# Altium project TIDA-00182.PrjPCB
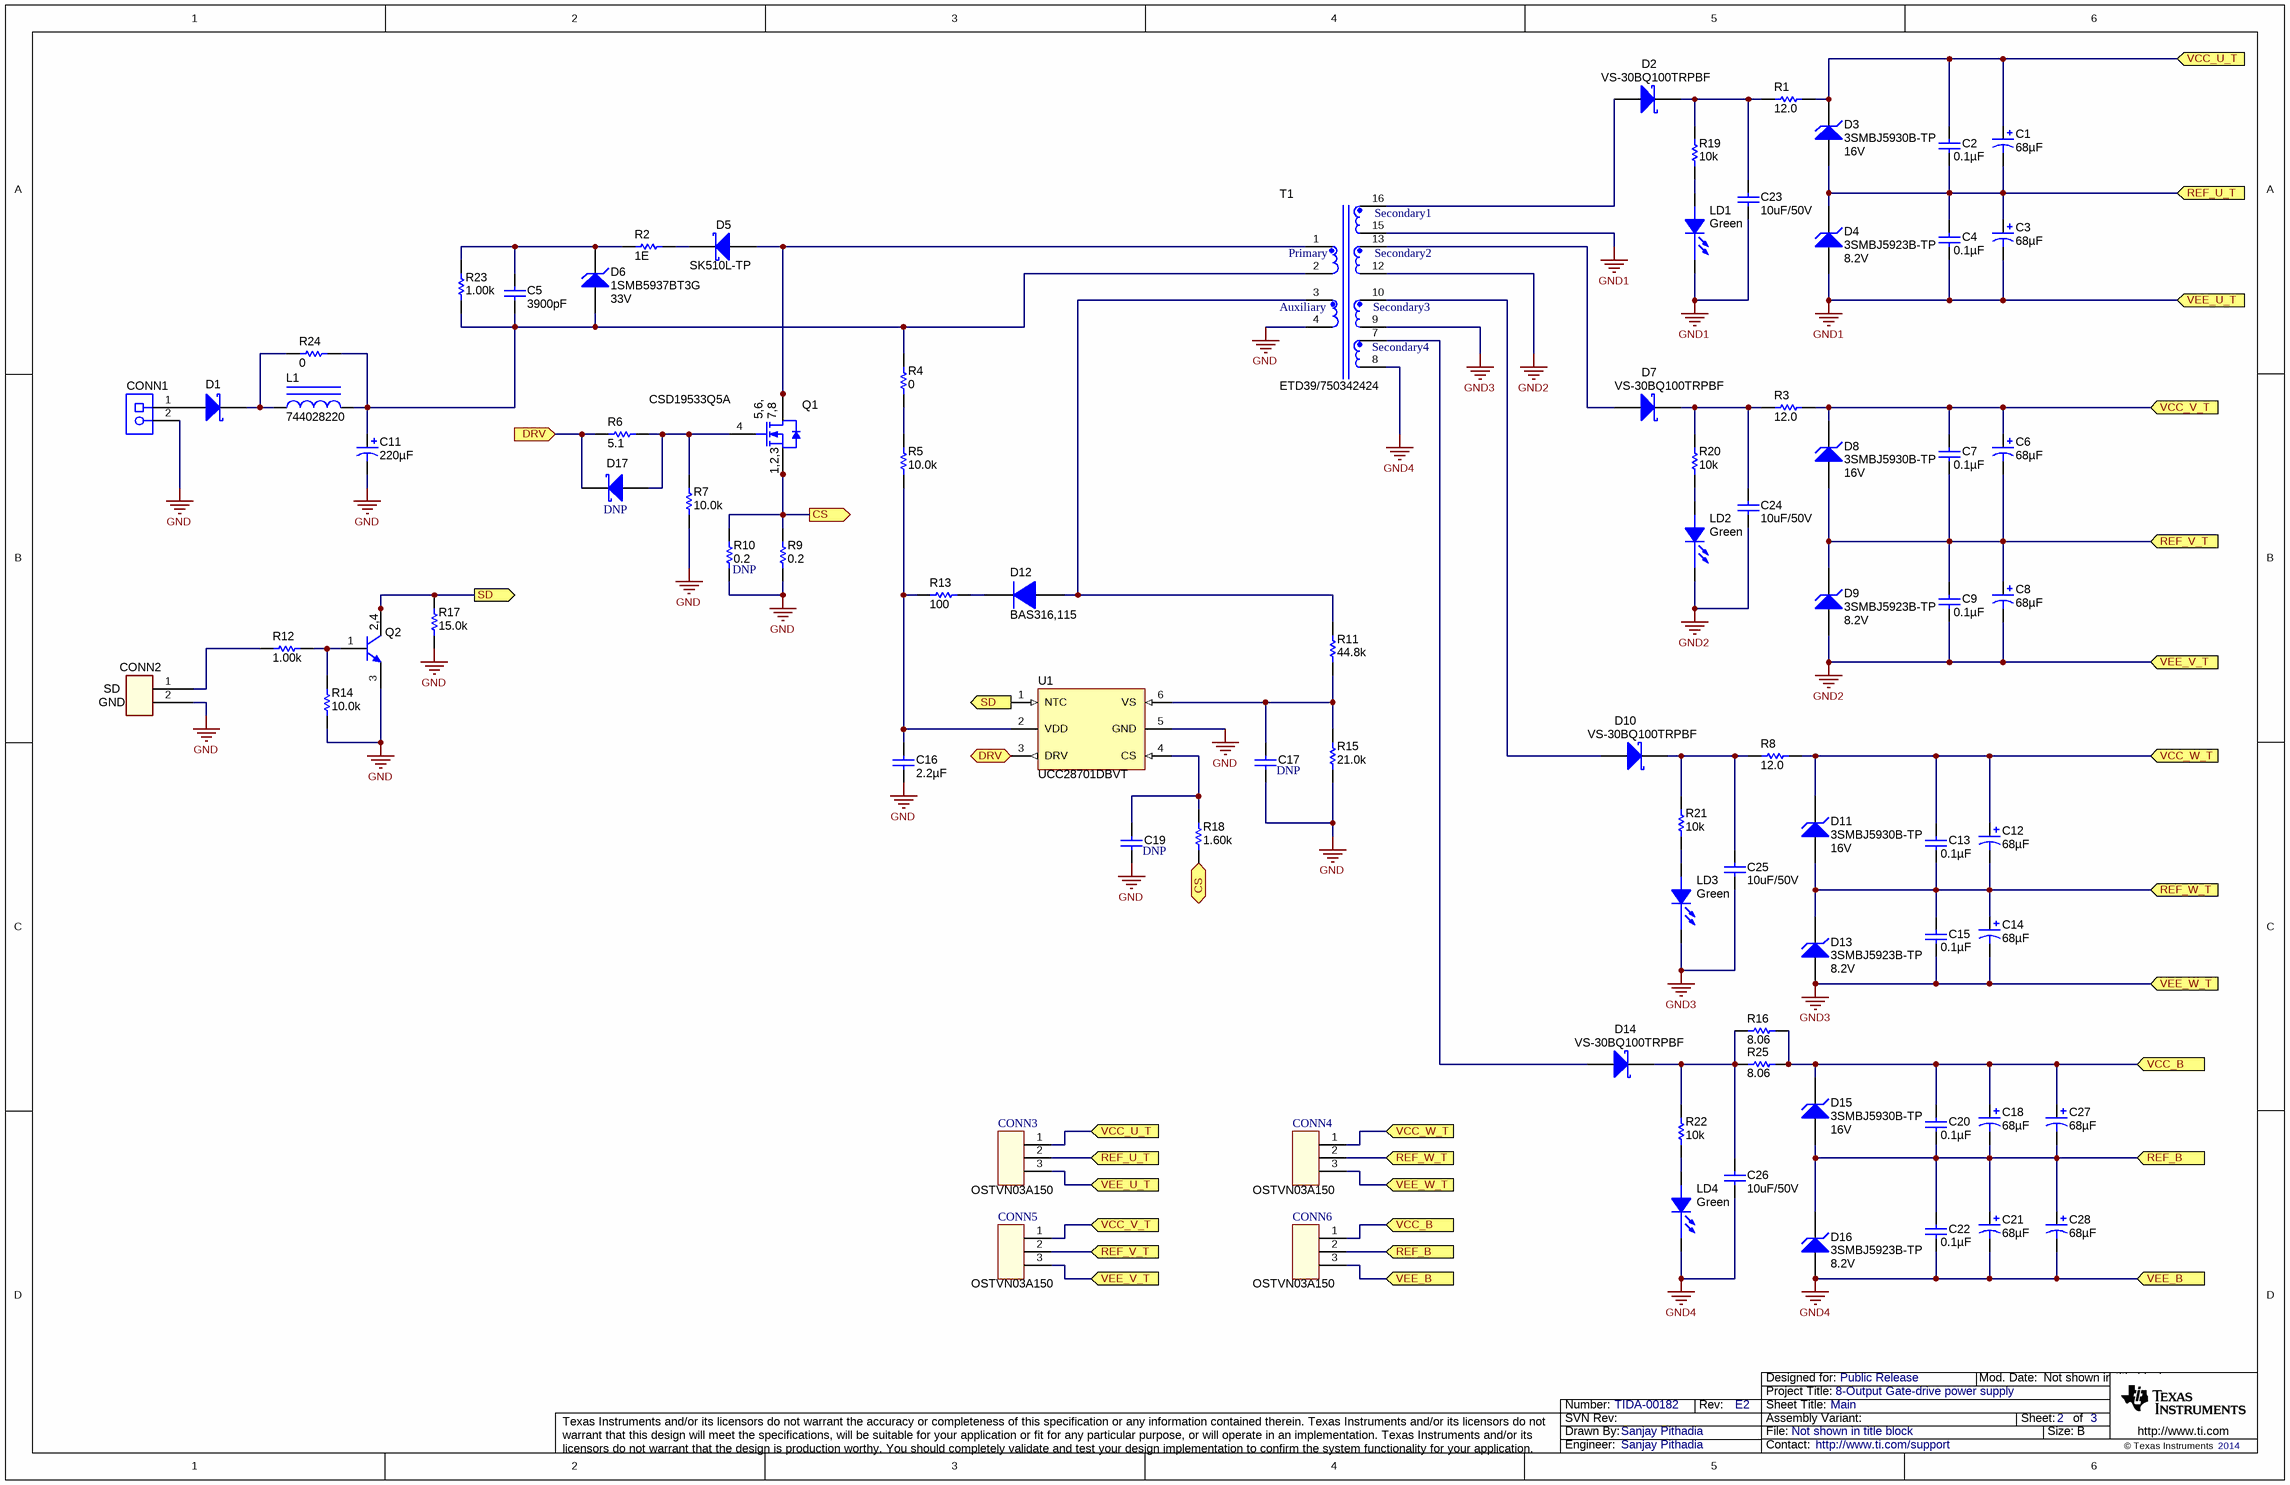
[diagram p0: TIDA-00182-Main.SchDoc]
CopyrightYear: 2014; PCB_Layout: Sharanu; PCB_Rev: E2; PRJ_Customer: Public Release; PRJ_Engineer: Sanjay Pithadia; PRJ_Number: TIDA-00182; PRJ_Title: 8-Output Gate-drive power supply; SCH_Rev: E2; TechSupport: http://www.ti.com/support
3 sheets, 102 parts. Net scope: flat (ports and power ports of the same name join across sheets).
Board file: TIDA-00182.PcbDoc
Sheets:
  TIDA-00182-Cover.SchDoc
  TIDA-00182-Main.SchDoc
  Hardware_ANSI-B.SchDoc

## Sheet TIDA-00182-Cover.SchDoc
size 431 x 279 mm; Date: Not shown in title block; ApprovedBy: Not shown in title block; CheckedBy: Not shown in title block; Author: Not shown in title block; CompanyName: Not shown in title block; Engineer: Not shown in title block; Organization: Not shown in title block; Address1: Not shown in title block; Address2: Not shown in title block; Address3: Not shown in title block; Address4: Not shown in title block; DocumentNumber: 1; Revision: Use project parameter SCH_Rev; SheetNumber: 1; SheetTotal: 3; PageSetup: Record=PageOptions|CenterHorizontal=True|CenterVertical=True|PrintScale=1.00|XCorrection=1.00|YCorrection=1.00|PrintKind=0|BorderSize=5000000|LeftOffset=0|BottomOffset=0|Orientation=2|PaperLength=1000|PaperWidth=1000|Scale=100|PaperSource=15|PrintQuality=600|MediaType=1|DitherType=10|PaperKind=Letter|PrintScaleMode=1

## Sheet TIDA-00182-Main.SchDoc: Main
size 431 x 279 mm; Date: Not shown in title block; ApprovedBy: Not shown in title block; CheckedBy: Not shown in title block; Author: Not shown in title block; CompanyName: Not shown in title block; DrawnBy: Sanjay Pithadia; Engineer: Not shown in title block; Organization: Not shown in title block; Address1: Not shown in title block; Address2: Not shown in title block; Address3: Not shown in title block; Address4: Not shown in title block; DocumentNumber: 2; Revision: Use project parameter SCH_Rev; SheetNumber: 2; SheetTotal: 3; PageSetup: Record=PageOptions|CenterHorizontal=True|CenterVertical=True|PrintScale=1.00|XCorrection=1.00|YCorrection=1.00|PrintKind=0|BorderSize=5000000|LeftOffset=0|BottomOffset=0|Orientation=2|PaperLength=1000|PaperWidth=1000|Scale=100|PaperSource=15|PrintQuality=600|MediaType=1|DitherType=10|PaperKind=Letter|PrintScaleMode=1

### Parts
C1  ValueDisplayed: 68µF  [SM_RADIAL_6.3BMM]  (hidden comment: EEH-ZA1V680XP)
C2  ValueDisplayed: 0.1µF  [0805_HV]  (hidden comment: 08055C104JAT2A)
C3  ValueDisplayed: 68µF  [SM_RADIAL_6.3BMM]  (hidden comment: EEH-ZA1V680XP)
C4  ValueDisplayed: 0.1µF  [0805_HV]  (hidden comment: 08055C104JAT2A)
C5  ValueDisplayed: 3900pF  [0805_HV]  (hidden comment: GRM219R72A392KA01D)
C6  ValueDisplayed: 68µF  [SM_RADIAL_6.3BMM]  (hidden comment: EEH-ZA1V680XP)
C7  ValueDisplayed: 0.1µF  [0805_HV]  (hidden comment: 08055C104JAT2A)
C8  ValueDisplayed: 68µF  [SM_RADIAL_6.3BMM]  (hidden comment: EEH-ZA1V680XP)
C9  ValueDisplayed: 0.1µF  [0805_HV]  (hidden comment: 08055C104JAT2A)
C11  ValueDisplayed: 220µF  [SM_RADIAL_F]  (hidden comment: EEE-FK1V221P)
C12  ValueDisplayed: 68µF  [SM_RADIAL_6.3BMM]  (hidden comment: EEH-ZA1V680XP)
C13  ValueDisplayed: 0.1µF  [0805_HV]  (hidden comment: 08055C104JAT2A)
C14  ValueDisplayed: 68µF  [SM_RADIAL_6.3BMM]  (hidden comment: EEH-ZA1V680XP)
C15  ValueDisplayed: 0.1µF  [0805_HV]  (hidden comment: 08055C104JAT2A)
C16  ValueDisplayed: 2.2µF  [0805_HV]  (hidden comment: C2012X5R1H225K125AB)
C17  Fitted: DNP  [0805_HV]  (hidden comment: 08053D334KAT2A)
C18  ValueDisplayed: 68µF  [SM_RADIAL_6.3BMM]  (hidden comment: EEH-ZA1V680XP)
C19  Fitted: DNP  [0805_HV]  (hidden comment: C2012X7R1H102K)
C20  ValueDisplayed: 0.1µF  [0805_HV]  (hidden comment: 08055C104JAT2A)
C21  ValueDisplayed: 68µF  [SM_RADIAL_6.3BMM]  (hidden comment: EEH-ZA1V680XP)
C22  ValueDisplayed: 0.1µF  [0805_HV]  (hidden comment: 08055C104JAT2A)
C23  10uF/50V  [1206_190]
C24  10uF/50V  [1206_190]
C25  10uF/50V  [1206_190]
C26  10uF/50V  [1206_190]
C27  ValueDisplayed: 68µF  [SM_RADIAL_6.3BMM]  (hidden comment: EEH-ZA1V680XP)
C28  ValueDisplayed: 68µF  [SM_RADIAL_6.3BMM]  (hidden comment: EEH-ZA1V680XP)
CONN1  282841-2  [TEC_282841-2]  (value not drawn)
CONN2  CON-OSTVN02A150  [CN2_MTB_P100_PD80_D1.1_S5.54X6.5_STACK]  (value not drawn)
CONN3  PartNumber: OSTVN03A150  [TB_OSTVN03A150_3P]  (hidden comment: CON-OSTVN03A150)
CONN4  PartNumber: OSTVN03A150  [TB_OSTVN03A150_3P]  (hidden comment: CON-OSTVN03A150)
CONN5  PartNumber: OSTVN03A150  [TB_OSTVN03A150_3P]  (hidden comment: CON-OSTVN03A150)
CONN6  PartNumber: OSTVN03A150  [TB_OSTVN03A150_3P]  (hidden comment: CON-OSTVN03A150)
D1  B260A-13-F  [SMA]  (value not drawn)
D2  VS-30BQ100TRPBF  [SMC]
D3  3SMBJ5930B-TP  value 16V  [SMB]
D4  3SMBJ5923B-TP  value 8.2V  [SMB]
D5  SK510L-TP  [SMC]
D6  1SMB5937BT3G  value 33V  [SMB]
D7  VS-30BQ100TRPBF  [SMC]
D8  3SMBJ5930B-TP  value 16V  [SMB]
D9  3SMBJ5923B-TP  value 8.2V  [SMB]
D10  VS-30BQ100TRPBF  [SMC]
D11  3SMBJ5930B-TP  value 16V  [SMB]
D12  BAS316,115  [sod-323]
D13  3SMBJ5923B-TP  value 8.2V  [SMB]
D14  VS-30BQ100TRPBF  [SMC]
D15  3SMBJ5930B-TP  value 16V  [SMB]
D16  3SMBJ5923B-TP  value 8.2V  [SMB]
D17  Fitted: DNP  [SOD-123]  (hidden comment: MBR0520LT1G)
L1  744028220  [WE-TPC_2811]
LD1  value Green  [LED0603AA]  (hidden comment: LED_LG L29K-G2J1-24-Z)
LD2  value Green  [LED0603AA]  (hidden comment: LED_LG L29K-G2J1-24-Z)
LD3  value Green  [LED0603AA]  (hidden comment: LED_LG L29K-G2J1-24-Z)
LD4  value Green  [LED0603AA]  (hidden comment: LED_LG L29K-G2J1-24-Z)
Q1  CSD19533Q5A  [TRANS_NexFET_Q5A]
Q2  2DD1664R-13  [SOT-89-3]  (value not drawn)
R1  value 12.0  [1206]  (hidden comment: RC1206FR-0712RL)
R2  value 1E  [1206]  (hidden comment: CRCW12061K00FKEA)
R3  value 12.0  [1206]  (hidden comment: RC1206FR-0712RL)
R4  value 0  [1206]  (hidden comment: RC1206JR-070RL)
R5  value 10.0k  [1206]  (hidden comment: ERJ-8ENF1002V)
R6  value 5.1  [0805_HV]  (hidden comment: CRCW08055R10JNEA)
R7  value 10.0k  [0805_HV]  (hidden comment: RG2012P-103-B-T5)
R8  value 12.0  [1206]  (hidden comment: RC1206FR-0712RL)
R9  value 0.2  [1206]  (hidden comment: CSR1206FKR200)
R10  value 0.2  Fitted: DNP  [1206]  (hidden comment: CSR1206FKR200)
R11  value 44.8k  [0805_HV]  (hidden comment: RT0805BRD0744K8L)
R12  value 1.00k  [0805_HV]  (hidden comment: CRCW08051K00FKEA)
R13  value 100  [0805_HV]  (hidden comment: CRCW0805100RFKEA)
R14  value 10.0k  [0805_HV]  (hidden comment: RG2012P-103-B-T5)
R15  value 21.0k  [0805_HV]  (hidden comment: CRCW080521K0FKEA)
R16  value 8.06  [1206]  (hidden comment: CRCW12068R06FKEA)
R17  value 15.0k  [0805_HV]  (hidden comment: RG2012P-153-B-T5)
R18  value 1.60k  [0805_HV]  (hidden comment: RR1220P-162-D)
R19  value 10k  [0805_HV]  (hidden comment: CRCW080510K0JNEA)
R20  value 10k  [0805_HV]  (hidden comment: CRCW080510K0JNEA)
R21  value 10k  [0805_HV]  (hidden comment: CRCW080510K0JNEA)
R22  value 10k  [0805_HV]  (hidden comment: CRCW080510K0JNEA)
R23  value 1.00k  [1206]  (hidden comment: RC1206FR-071KL)
R24  value 0  [1206]  (hidden comment: RC1206JR-070RL)
R25  value 8.06  [1206]  (hidden comment: CRCW12068R06FKEA)
T1  ETD39/750342424  [XFORMER_ETD39]
U1  UCC28701DBVT  [DBV-6]

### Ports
CS (in), CS (out), DRV (in), DRV (out), REF_B, REF_U_T, REF_V_T, REF_W_T, SD (in), SD (out), VCC_B, VCC_U_T, VCC_V_T, VCC_W_T, VEE_B, VEE_U_T, VEE_V_T, VEE_W_T

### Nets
GND: C11.2(-) C16.2 C17.2 C19.2 CONN1.2 CONN2.2 Q2.3(E) R7.1 R9.1 R10.1 R14.1 R15.1 R17.1 T1.4 U1.5(GND)
GND1: C3.2(-) C4.2 C23.2 CONN3.3 D4.2(A) LD1.1(C) T1.15 ; port VEE_U_T
GND2: C8.2(-) C9.2 C24.2 CONN5.3 D9.2(A) LD2.1(C) T1.12 ; port VEE_V_T
GND3: C14.2(-) C15.2 C25.2 CONN4.3 D13.2(A) LD3.1(C) T1.9 ; port VEE_W_T
GND4: C21.2(-) C22.2 C26.2 C28.2(-) CONN6.3 D16.2(A) LD4.1(C) T1.8 ; port VEE_B
CS: Q1.1(S) Q1.2(S) Q1.3(S) R9.2 R10.2 R18.1 ; port CS
DRV: D17.1(K) R6.2 U1.3(DRV) ; port DRV
REF_B: C18.2(-) C20.2 C21.1(+) C22.1 C27.2(-) C28.1(+) CONN6.2 D15.2(A) D16.1(K) ; port REF_B
REF_U_T: C1.2(-) C2.2 C3.1(+) C4.1 CONN3.2 D3.2(A) D4.1(K) ; port REF_U_T
REF_V_T: C6.2(-) C7.2 C8.1(+) C9.1 CONN5.2 D8.2(A) D9.1(K) ; port REF_V_T
REF_W_T: C12.2(-) C13.2 C14.1(+) C15.1 CONN4.2 D11.2(A) D13.1(K) ; port REF_W_T
SD: Q2.2(C) Q2.4(C) R17.2 U1.1(NTC) ; port SD
VCC_B: C18.1(+) C20.1 C27.1(+) CONN6.1 D15.1(K) R16.2 R25.2 ; port VCC_B
VCC_U_T: C1.1(+) C2.1 CONN3.1 D3.1(K) R1.2 ; port VCC_U_T
VCC_V_T: C6.1(+) C7.1 CONN5.1 D8.1(K) R3.2 ; port VCC_V_T
VCC_W_T: C12.1(+) C13.1 CONN4.1 D11.1(K) R8.2 ; port VCC_W_T
NetC5_1: C5.1 D6.1(K) R2.1 R23.2
NetC5_2: C5.2 C11.1(+) D6.2(A) L1.2 R4.2 R23.1 R24.1 T1.2
NetC16_1: C16.1 R5.1 R13.1 U1.2(VDD)
NetC17_1: C17.1 R11.1 R15.2 U1.6(VS)
NetC19_1: C19.1 R18.2 U1.4(CS)
NetC23_1: C23.1 D2.1(K) R1.1 R19.1
NetC24_1: C24.1 D7.1(K) R3.1 R20.1
NetC25_1: C25.1 D10.1(K) R8.1 R21.1
NetC26_1: C26.1 D14.1(K) R16.1 R22.1 R25.1
NetCONN1_1: CONN1.1 D1.2(A)
NetCONN2_1: CONN2.1 R12.2
NetD1_1: D1.1(K) L1.1 R24.2
NetD2_2: D2.2(A) T1.16
NetD5_1: D5.1(K) R2.2
NetD5_2: D5.2(A) Q1.5(D) Q1.6(D) Q1.7(D) Q1.8(D) Q1.9(D) T1.1
NetD7_2: D7.2(A) T1.13
NetD10_2: D10.2(A) T1.10
NetD12_1: D12.1(K) R13.2
NetD12_2: D12.2(A) R11.2 T1.3
NetD14_2: D14.2(A) T1.7
NetD17_2: D17.2(A) Q1.4(G) R6.1 R7.2
NetLD1_2: LD1.2(A) R19.2
NetLD2_2: LD2.2(A) R20.2
NetLD3_2: LD3.2(A) R21.2
NetLD4_2: LD4.2(A) R22.2
NetQ2_1: Q2.1(B) R12.1 R14.2
NetR4_1: R4.1 R5.2

Not connected (* = marked no-connect by the designer): T1 5 6 11 14

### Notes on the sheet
- (near CONN2) SD
- (near CONN2) GND

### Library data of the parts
C1 C3 C6 C8 C12 C14 C18 C21 C27 C28 = UUD1V680MCL1GS: CAP ALUM 68UF 35V 20% SMD; Manufacturer: Panasonic Electronic Components; Polarized: Y; CompType: Capacitor; U/M: EA; Cap_F: 0.000068; Tolerance_%: 20; Value1: 0.34 ohm; VDC_V: 35; ESR_Ohm: 0.34; IRMS_A: 0.28; TaMin_C: -55; TaMax_C: 105; Cap_Case: 6.60mm x 6.60mm
C2 C4 C7 C9 C13 C15 C20 C22 = 08055C104JAT2A: CAP, CERM, 0.1uF, 50V, +/-5%, X7R, 0805; Manufacturer: AVX; Polarized: N; CompType: Capacitor; U/M: EA; Cap_F: 0.0000001; Tolerance_%: 5; ESR_Ohm: 0.024; Value1: 0.024 ohm; VDC_V: 50; TaMin_C: -55; TaMax_C: 125; Cap_Case: 0805
C5 = GRM219R72A392KA01D: CAP, CERM, 3900pF, 100V, +/-10%, X7R, 0805; Manufacturer: MuRata; Polarized: N; CompType: Capacitor; U/M: EA; Cap_F: 0.0000000039; Tolerance_%: 10; Value1: Unknown; VDC_V: 100; TaMin_C: -55; TaMax_C: 125; Cap_Case: 0805
C11 = EEE-FK1V221P: CAP, AL, 220uF, 35V, +/-20%, 0.16 ohm, SMD; Manufacturer: Panasonic; Polarized: Y; CompType: Capacitor; U/M: EA; Cap_F: 0.00022; Tolerance_%: 20; VDC_V: 35; ESR_Ohm: 0.16; IRMS_A: 0.6; TaMin_C: -55; TaMax_C: 105; Cap_Case: F
C16 = C2012X5R1H225K125AB: CAP, CERM, 2.2uF, 50V, +/-10%, X5R, 0805; Manufacturer: TDK; Polarized: N; CompType: Capacitor; U/M: EA; Cap_F: 0.0000022; Tolerance_%: 10; Value1: Unknown; VDC_V: 50; TaMin_C: -55; TaMax_C: 85; Cap_Case: 0805
C17 = 08053D334KAT2A: CAP, CERM, 0.33uF, 25V, +/-10%, X5R, 0805; Manufacturer: AVX; Polarized: N; CompType: Capacitor; ValueDisplayed: 0.33µF; U/M: EA; Cap_F: 0.00000033; Tolerance_%: 10; ESR_Ohm: 0.02; Value1: 0.02 ohm; VDC_V: 25; TaMin_C: -55; TaMax_C: 85; Cap_Case: 0805
C19 = C2012X7R1H102K: CAP, CERM, 1000pF, 50V, +/-10%, X7R, 0805; Manufacturer: TDK; Polarized: N; CompType: Capacitor; U/M: EA; Cap_F: 0.000000001; Tolerance_%: 10; ESR_Ohm: 0.28; Value1: 0.28 ohm; VDC_V: 50; TaMin_C: -55; TaMax_C: 125; Cap_Case: 0805
C23-C26 = CGA5L3X5R1H106K160AB: CAP, CERM, 10uF, 50V, +/-10%, X5R, 1206_190; Manufacturer: TDK; Polarized: N; CompType: Capacitor; ValueDisplayed: 10µF; U/M: EA; Cap_F: 0.00001; Tolerance_%: 10; Value1: Unknown; VDC_V: 50; TaMin_C: -55; TaMax_C: 85
CONN1 = 282841-2: Terminal Block, 2x1, 5.08mm, TH; Manufacturer: TE Connectivity; SymbolCreator: a0412235; U/M: EA
CONN2 = CON-OSTVN02A150: Terminal Block, 4x1, 2.54mm, TH; Manufacturer: On Shore Technology Inc; SymbolCreator: x0120606
CONN3-CONN6 = CON-OSTVN03A150: CONN TERM BLOCK 2.54MM 3POS PCB; Manufacturer: On Shore Technology Inc; SymbolCreator: x0120606; CompType: Terminal Block
D1 = B260A-13-F: Diode, Schottky, 60V, 2A, SMA; Manufacturer: Diodes Inc.; U/M: EA; Vf_V: 0.7; Value2: 0.7V; Io_A: 2; Vr_V: 60; TJmax_C: 150; RJC_CperW: 20
D2 D7 D10 D14 = VS-30BQ100TRPBF: Diode, Schottky, 100V, 3A, SMC; Manufacturer: Vishay-Semiconductor; U/M: EA; Vf_V: 0.62; Value2: 0.62V; Io_A: 3; Vr_V: 100; TJmax_C: 175; RJC_CperW: 46
D3 D8 D11 D15 = 1SMB5930BT3G: DIODE ZENER 16V 3W DO214AA; Manufacturer: Micro Commercial Co; SymbolCreator: a0412235; U/M: EA; Power_W: 3; Vz_V: 16; RJA_CperW: 226
D4 D9 D13 D16 = 1SMB5930BT3G: DIODE ZENER 8.2V 3W DO214AA; Manufacturer: Micro Commercial Co; SymbolCreator: a0412235; U/M: EA; Power_W: 3; Vz_V: 16; RJA_CperW: 226
D5 = MBRS3100T3G: DIODE SCHOTTKY 100V 5A DO214AB; Manufacturer: Micro Commercial Co; U/M: EA; Vf_V: 0.62; Value2: 0.62V; Io_A: 3; Vr_V: 100; TJmax_C: 150; RJC_CperW: 11
D6 = 1SMB5937BT3G: Diode, Zener, 33V, 550mW, SMB; Manufacturer: ON Semiconductor; SymbolCreator: a0412235; U/M: EA; Power_W: 0.55; Vz_V: 33; Value1: 0.55W; RJA_CperW: 226
D12 = BAS316,115: Diode, Ultrafast, 100V, 0.25A, SOD-323; Manufacturer: NXP Semiconductor; U/M: EA; Vf_V: 1.4; Value2: 1.4V; Io_A: 0.25; Vr_V: 100; TJmax_C: 150
D17 = MBR0520LT1G: Diode, Schottky, 20V, 0.5A, SOD-123; Manufacturer: ON Semiconductor; U/M: EA; Vf_V: 0.385; Value2: 0.385V; Io_A: 0.5; Vr_V: 20; TJmax_C: 125; RJC_CperW: 150
L1 = 744028220: Inductor, Shielded Drum Core, Ferrite, 22uH, 0.27A, 1.22 ohm, SMD; Manufacturer: Wurth Elektronik eiSos; Ind_H: 22.0E-6; ValueDisplayed: 22µH; Imax_A: 0.27; Irms: 0.35A @ 40C rise; Isat: 0.27A @ 35% inductance drop; DCR_ohm: 1.22; U/M: EA
LD1-LD4 = LED_LG L29K-G2J1-24-Z: LED SmartLED Green 570NM; Manufacturer: OSRAM; SymbolCreator: x0120606
Q1 = CSD19533Q5A: MOSFET, N-CH, 100V, 13A, SON 5x6mm; Manufacturer: Texas Instruments; Alternate Manufacturer: None; U/M: EA; ChType: N; VdsMax_V: 100; Value1: ? ohm; Value2: 27 nC; QgTyp_nC: 27; Vgs_V: 20; IdsMax_A: 13
Q2 = 2DD1664R-13, Diodes Inc.: Transistor, NPN, 32V, 1A, SOT-89; CompType: BJT; PNP: 0; NPN: 1; Vceo_V: 32; Vcesat1_V: 0.4; Value: 0.4V; HfeMax: 390; TaMin_C: -55; TaMax_C: 150; U/M: EA
R1 R3 R8 = RC1206FR-0712RL: RES, 12.0 ohm, 1%, 0.25W, 1206; Manufacturer: Yageo America; CompType: Resistor; Res_ohm: 12; Value_Code: 12R0; Tolerance_%: 1; Power_W: 0.25; VDC_V: 200; TempCo: 100 ppm/C; U/M: EA
R2 = CRCW12061K00FKEA: RES, 1.00 ohm, 1%, 0.25W, 1206; Manufacturer: Vishay-Dale; CompType: Resistor; Res_ohm: 1000; Value_Code: 1k00; Tolerance_%: 1; Power_W: 0.25; VDC_V: 200; TempCo: 100 ppm/C; EIA_Code: E96; U/M: EA
R4 R24 = RC1206JR-070RL: RES, 0 ohm, 5%, 0.25W, 1206; Manufacturer: Yageo America; CompType: Resistor; Value_Code: 0000; Tolerance_%: 5; Power_W: 0.25; VDC_V: 200; TempCo: 200 ppm/C; EIA_Code: E24; U/M: EA
R5 = ERJ-8ENF1002V: RES, 10.0k ohm, 1%, 0.25W, 1206; Manufacturer: Panasonic; CompType: Resistor; Res_ohm: 10000; Value_Code: 10k0; Tolerance_%: 1; Power_W: 0.25; VDC_V: 200; TempCo: 100 ppm/C; EIA_Code: E96; U/M: EA
R6 = CRCW08055R10JNEA: RES, 5.1 ohm, 5%, 0.125W, 0805; Manufacturer: Vishay-Dale; CompType: Resistor; Value_Code: 5R10; Tolerance_%: 5; Power_W: 0.125; VDC_V: 150; TempCo: 200 ppm/C; EIA_Code: E24; U/M: EA
R7 R14 = RG2012P-103-B-T5: RES, 10.0k ohm, 0.1%, 0.125W, 0805; Manufacturer: Susumu Co Ltd; CompType: Resistor; Res_ohm: 10000; Value_Code: 10k0; Tolerance_%: 0.1; Power_W: 0.125; VDC_V: 100; TempCo: 25 ppm/C; EIA_Code: E192; U/M: EA
R9 R10 = CSR1206FKR200: RES, 0.2 ohm, 1%, 0.5W, 1206; Manufacturer: Stackpole Electronics Inc; CompType: Resistor; Value_Code: R200; Tolerance_%: 1; Power_W: 0.5; TempCo: 100 ppm/C; EIA_Code: E96; U/M: EA
R11 = RT0805BRD0744K8L: RES, 44.8k ohm, 0.1%, 0.125W, 0805; Manufacturer: Yageo America; CompType: Resistor; Res_ohm: 44800; Value_Code: 44k8; Tolerance_%: 0.1; Power_W: 0.125; VDC_V: 150; TempCo: 25 ppm/C; EIA_Code: E192; U/M: EA
R12 = CRCW08051K00FKEA: RES, 1.00k ohm, 1%, 0.125W, 0805; Manufacturer: Vishay-Dale; CompType: Resistor; Res_ohm: 1000; Value_Code: 1k00; Tolerance_%: 1; Power_W: 0.125; VDC_V: 150; TempCo: 100 ppm/C; EIA_Code: E96; U/M: EA
R13 = CRCW0805100RFKEA: RES, 100 ohm, 1%, 0.125W, 0805; Manufacturer: Vishay-Dale; CompType: Resistor; Value_Code: 100R; Tolerance_%: 1; Power_W: 0.125; VDC_V: 150; TempCo: 100 ppm/C; EIA_Code: E96; U/M: EA
R15 = CRCW080521K0FKEA: RES, 21.0k ohm, 1%, 0.125W, 0805; Manufacturer: Vishay-Dale; CompType: Resistor; Res_ohm: 21000; Value_Code: 21k0; Tolerance_%: 1; Power_W: 0.125; VDC_V: 150; TempCo: 100 ppm/C; EIA_Code: E96; U/M: EA
R16 R25 = CRCW12068R06FKEA: RES, 8.06 ohm, 1%, 0.25W, 1206; Manufacturer: Vishay-Dale; CompType: Resistor; Value_Code: 8R06; Tolerance_%: 1; Power_W: 0.25; VDC_V: 200; TempCo: 100 ppm/C; EIA_Code: E96; U/M: EA
R17 = RG2012P-153-B-T5: RES, 15.0k ohm, 0.1%, 0.125W, 0805; Manufacturer: Susumu Co Ltd; CompType: Resistor; Res_ohm: 15000; Value_Code: 15k0; Tolerance_%: 0.1; Power_W: 0.125; VDC_V: 100; TempCo: 25 ppm/C; EIA_Code: E192; U/M: EA
R18 = RR1220P-162-D: RES, 1.60k ohm, 0.5%, 0.1W, 0805; Manufacturer: Susumu Co Ltd; CompType: Resistor; Res_ohm: 1600; Value_Code: 1k60; Tolerance_%: 0.5; Power_W: 0.1; VDC_V: 100; TempCo: 25 ppm/C; EIA_Code: E192; U/M: EA
R19-R22 = CRCW080510K0JNEA: RES, 10k ohm, 5%, 0.125W, 0805; Manufacturer: Vishay-Dale; CompType: Resistor; Res_ohm: 10000; Value_Code: 10k0; Tolerance_%: 5; Power_W: 0.125; VDC_V: 150; TempCo: 200 ppm/C; EIA_Code: E24; U/M: EA
R23 = RC1206FR-071KL: RES, 1.00k ohm, 1%, 0.25W, 1206; Manufacturer: Yageo America; CompType: Resistor; Res_ohm: 1000; Value_Code: 1k00; Tolerance_%: 1; Power_W: 0.25; VDC_V: 200; TempCo: 100 ppm/C; EIA_Code: E96; U/M: EA
T1 = ETD39/750342366: Transformer,   TH; Manufacturer: wurth elektronik; SymbolCreator: a0411947; U/M: EA
U1 = UCC28701DBV: IC, Constant Voltage, Constant Current PWM With Primary Side Regulation; Manufacturer: TI; SymbolCreator: a0411947; CompType: Transformer; Value: UCC2871xDBV; U/M: EA

## Sheet Hardware_ANSI-B.SchDoc
size 431 x 279 mm; Date: Not shown in title block; ApprovedBy: Not shown in title block; CheckedBy: Not shown in title block; Author: Not shown in title block; CompanyName: Not shown in title block; Engineer: Not shown in title block; Organization: Not shown in title block; Address1: Not shown in title block; Address2: Not shown in title block; Address3: Not shown in title block; Address4: Not shown in title block; DocumentNumber: 3; Revision: Use project parameter SCH_Rev; SheetNumber: 3; SheetTotal: 3; PageSetup: Record=PageOptions|CenterHorizontal=True|CenterVertical=True|PrintScale=1.00|XCorrection=1.00|YCorrection=1.00|PrintKind=0|BorderSize=5000000|LeftOffset=0|BottomOffset=0|Orientation=2|PaperLength=1000|PaperWidth=1000|Scale=100|PaperSource=15|PrintQuality=600|MediaType=1|DitherType=10|PaperKind=Letter|PrintScaleMode=1
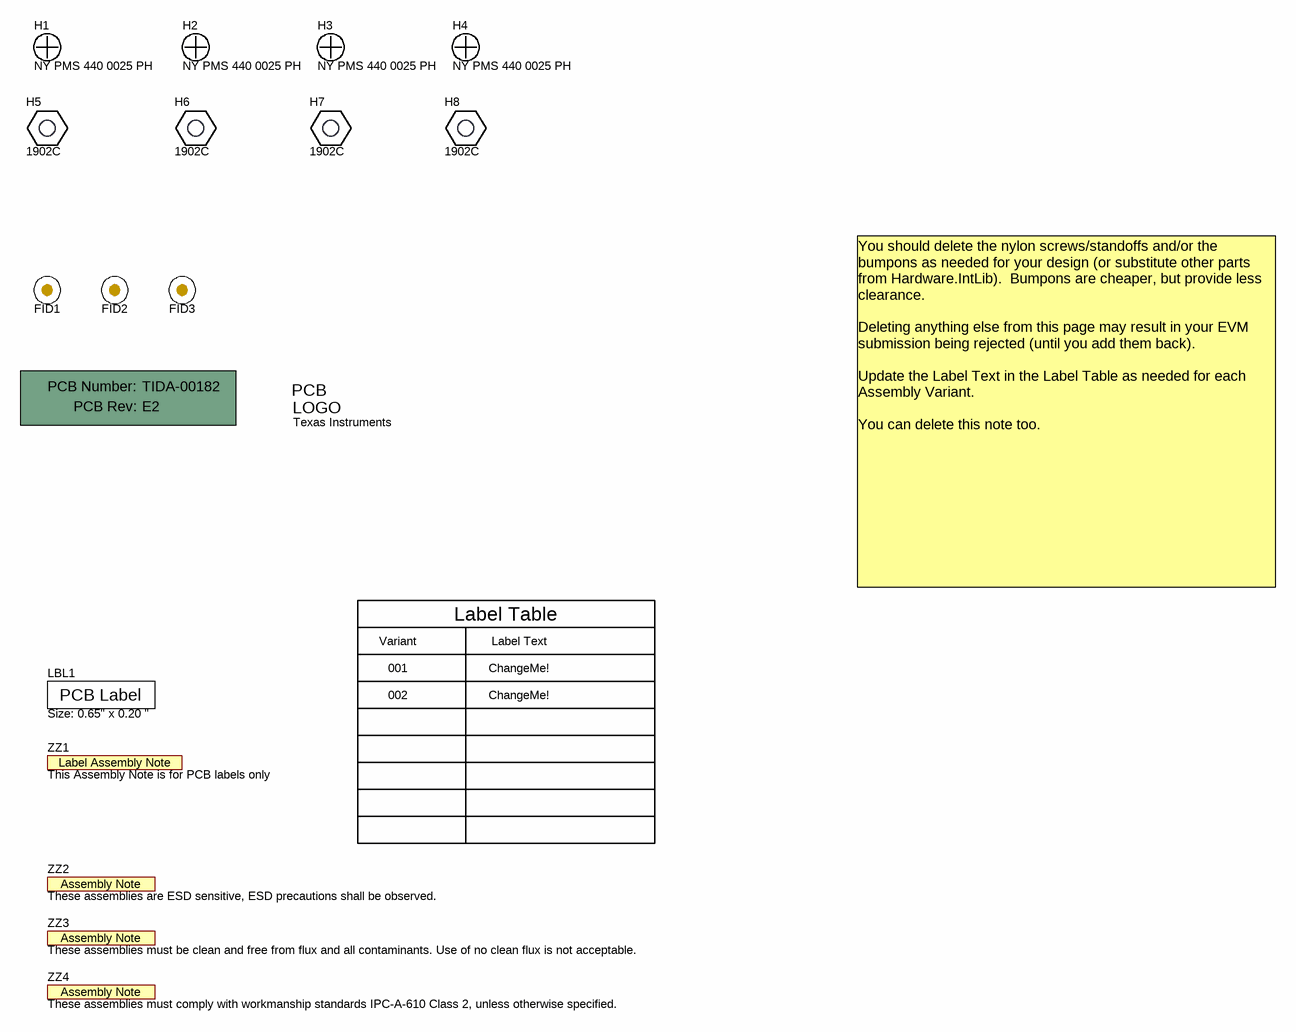
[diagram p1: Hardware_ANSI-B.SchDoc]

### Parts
!PCB  Printed Circuit Board  (value not drawn)  (mechanical)
FID1  Fiducial  [Fiducial10-20]  (value not drawn)
FID2  Fiducial  [Fiducial10-20]  (value not drawn)
FID3  Fiducial  [Fiducial10-20]  (value not drawn)
H1  NY PMS 440 0025 PH  [NY PMS 440 0025 PH]
H2  NY PMS 440 0025 PH  [NY PMS 440 0025 PH]
H3  NY PMS 440 0025 PH  [NY PMS 440 0025 PH]
H4  NY PMS 440 0025 PH  [NY PMS 440 0025 PH]
H5  1902C  [Keystone_1902C]
H6  1902C  [Keystone_1902C]
H7  1902C  [Keystone_1902C]
H8  1902C  [Keystone_1902C]
LBL1  Size: 0.65" x 0.20 "  [Label_650x200]
Logo1  Texas Instruments  [TI_Stacked_SolderMask_Small]  (no BOM)
ZZ1  This Assembly Note is for PCB labels only  [AssemblyNoteLabel]  (no BOM)
ZZ2  These assemblies are ESD sensitive, ESD precautions shall be observed.  [AssemblyNote]  (no BOM)
ZZ3  These assemblies must be clean and free from flux and all contaminants. Use of no clean flux is not acceptable.  [AssemblyNote]  (no BOM)
ZZ4  These assemblies must comply with workmanship standards IPC-A-610 Class 2, unless otherwise specified.  [AssemblyNote]  (no BOM)

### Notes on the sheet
- Variant
- Label Table
- Label Text
- You should delete the nylon screws/standoffs and/or the bumpons as needed for your design (or substitute other parts from Hardware.IntLib).  Bumpons are cheaper, but provide less clearance.
  Deleting anything else from this page may result in your EVM submission being rejected (until you add them back).
  Update the Label Text in the Label Table as needed for each Assembly Variant.
  You can delete this note too.
- 001
- 002
- ChangeMe!

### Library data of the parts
!PCB = PCB: Manufacturer: Any; PartNumber: TIDA-00182; SymbolCreator: a0412235
FID1-FID3 = Fiducial: Fiducial mark.  There is nothing to buy or mount.; SymbolCreator: codlsc
H1-H4 = NY PMS 440 0025 PH: Machine Screw, Round, #4-40 x 1/4, Nylon, Philips panhead; Manufacturer: B&F Fastener Supply; CompType: Hardware; SymbolCreator: codlsc; U/M: EA
H5-H8 = 1902C: Standoff, Hex, 0.5"L #4-40 Nylon; Manufacturer: Keystone; CompType: Hardware
LBL1 = THT-14-423-10: Thermal Transfer Printable Labels, 0.650" W x 0.200" H - 10,000 per roll; Manufacturer: Brady; SymbolCreator: a0412235; CompType: Label
Logo1 = TI_Logo: Texas Instrument Corporate Signature; SymbolCreator: codlsc
ZZ1 = AssemblyNoteLabel: SymbolCreator: a0412235
ZZ2-ZZ4 = AssemblyNote: SymbolCreator: codlsc

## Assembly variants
001: not fitted C17 C19 D17 FID1 FID2 FID3 L1 R10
